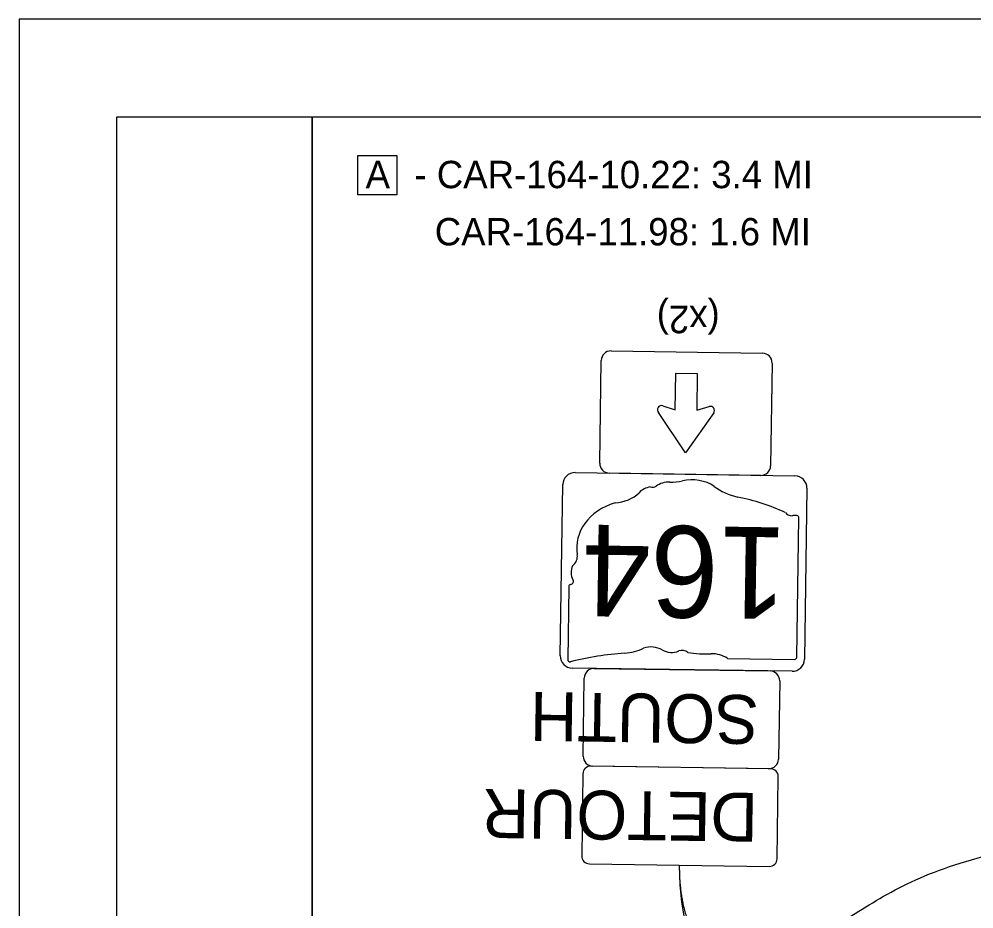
# Model space of a CAD drawing. Extents: x 0 to 1214, y 0 to 883.
# Drawn here: x 0 to 97.7, y 349 to 440 of the extents above; entities that cross this region are included whole.
import ezdxf

# ---------------------------------------------------------------- set-up
doc = ezdxf.new("R2010")
doc.units = 0
for name, color, linetype in [('GM_X_Minor_River', 7, 'Continuous'), ('GM_X_Section', 7, 'Continuous'), ('SH_Border', 7, 'Continuous'), ('SH_Cut_Line', 7, 'Continuous'), ('SH_Data', 7, 'Continuous')]:
    doc.layers.add(name, color=color, linetype=linetype)

msp = doc.modelspace()

# ---------------------------------------------------------------- linework, layer by layer
at = {"layer": 'GM_X_Minor_River'}
for p, q in [((60.603, 406.048), (76.102, 405.82)), ((59.434, 394.564), (59.589, 405.063)), ((77.087, 404.805), (76.932, 394.306)), ((67.172, 400.014), (67.227, 403.763)), ((67.227, 403.763), (69.415, 403.731)), ((69.415, 403.731), (69.36, 399.982)), ((65.894, 400.431), (67.172, 400.014)), ((69.36, 399.982), (70.647, 400.361)), ((68.2, 395.623), (65.466, 399.744)), ((71.104, 399.719), (68.2, 395.623)), ((75.917, 393.321), (60.419, 393.549)), ((79.613, 374.736), (79.823, 388.965)), ((56.28, 381.928), (56.17, 374.484)), ((56.282, 381.926), (56.28, 381.928)), ((72.516, 374.596), (79.379, 374.495)), ((58.874, 373.57), (76.873, 373.305)), ((57.742, 364.586), (57.86, 372.585)), ((77.858, 372.29), (77.74, 364.291)), ((76.725, 363.306), (58.727, 363.571))]:
    msp.add_line(p, q, dxfattribs=at)
for points in [[(56.919, 393.601), (79.417, 393.269)], [(55.393, 374.871), (55.651, 392.369)], [(80.648, 392.001), (80.391, 374.503)], [(79.122, 373.271), (56.625, 373.603)], [(57.715, 362.786), (57.592, 354.387)], [(76.925, 363.303), (58.527, 363.574)], [(77.589, 354.092), (77.713, 362.491)], [(58.38, 353.575), (76.778, 353.304)]]:
    msp.add_lwpolyline(points, dxfattribs=at)
for centre, radius, start, end in [((60.588, 405.048), 1, 89.1557, 179.1557), ((76.087, 404.819), 1, 359.1557, 89.1557), ((65.765, 400.034), 0.417, 71.95109, 224.16526), ((70.765, 399.96), 0.417, 324.56692, 106.36031), ((60.434, 394.549), 1, 179.1557, 269.1557), ((75.932, 394.32), 1, 269.1557, 359.1557), ((56.901, 392.351), 1.25, 89.1557, 179.1557), ((79.399, 392.019), 1.25, 359.1557, 89.1557), ((56.643, 374.853), 1.25, 179.1557, 269.1557), ((79.141, 374.521), 1.25, 269.1557, 359.1557), ((58.86, 372.57), 1, 89.1557, 179.1557), ((76.858, 372.305), 1, 359.1557, 89.1557), ((58.742, 364.571), 1, 179.1557, 269.1557), ((76.74, 364.306), 1, 269.1557, 359.1557), ((58.515, 362.774), 0.8, 89.1557, 179.1557), ((76.913, 362.503), 0.8, 359.1557, 89.1557), ((58.392, 354.375), 0.8, 179.1557, 269.1557), ((76.79, 354.104), 0.8, 269.1557, 359.1557)]:
    msp.add_arc(centre, radius, start, end, dxfattribs=at)
for centre, major_axis, start_param, end_param in [((68.858, 390.019), (-3.563, 0.053), 4.026481, 4.996735), ((65.057, 390.562), (-2.008, 0.03), 4.937069, 5.64225), ((64.858, 392.522), (-0.535, 0.008), 1.147584, 2.315152), ((66.555, 391.119), (-1.898, 0.028), 4.691044, 5.507374), ((66.872, 394.969), (-2.928, 0.043), 1.495662, 1.94098), ((75.012, 395.43), (-5.615, 0.083), 0.823519, 1.323587), ((60.782, 393.242), (-3.404, 0.05), 1.647645, 2.488434), ((69.391, 377.153), (-17.947, 0.264), 4.195997, 4.488961), ((63.295, 385.887), (-6.216, 0.092), 5.101752, 6.440018), ((79.095, 389.797), (-0.754, 0.011), 0.519207, 1.627899), ((79.49, 387.545), (-2.09, 0.031), 4.665946, 4.897461), ((79.553, 389.001), (-0.274, 0.004), 3.00124, 4.508301), ((55.391, 385.056), (-1.763, 0.026), 2.387724, 3.262537), ((58.93, 383.376), (-2.424, 0.036), 5.934695, 6.695948), ((56.558, 381.952), (-0.279, 0.004), 5.05454, 6.418171), ((56.348, 382.473), (-0.404, 0.006), 1.883978, 3.671073), ((61.417, 379.106), (-5, 0.074), 1.699011, 2.107814), ((64.702, 374.241), (-1.9, 0.028), 4.081561, 5.145723), ((66.774, 376.466), (-1.579, 0.023), 0.950623, 2.079405), ((67.865, 374.805), (-0.76, 0.011), 3.836095, 5.185415), ((56.429, 374.449), (-0.261, 0.004), 6.141152, 7.989035), ((64.237, 355.314), (-24.852, 0.366), 4.814394, 5.042369), ((70.126, 382.621), (-9.453, 0.139), 1.404758, 1.657858), ((70.857, 372.968), (-2.633, 0.039), 4.042523, 4.731795), ((79.344, 374.71), (-0.271, 0.004), 1.712693, 3.28349)]:
    msp.add_ellipse(centre, major_axis=major_axis, ratio=0.8, start_param=start_param, end_param=end_param, dxfattribs=at)
at = {"layer": 'GM_X_Section'}
msp.add_lwpolyline([(34.671, 426.037), (38.671, 426.037), (38.671, 422.037), (34.671, 422.037)], close=True, dxfattribs=at)
at = {"layer": 'SH_Border'}
for points in [[(10, 430), (30, 430), (30, 10), (10, 10)], [(30, 430), (670, 430), (670, 10), (30, 10)]]:
    msp.add_lwpolyline(points, close=True, dxfattribs=at)
at = {"layer": 'SH_Cut_Line'}
msp.add_lwpolyline([(0, 0), (680, 0), (680, 440), (0, 440)], close=True, dxfattribs=at)
at = {"layer": 'SH_Data'}
for points, degree in [([(67.579, 353.439), (67.579, 345.589), (76.872, 342.327), (95.836, 355.671), (148.431, 361.305), (164.284, 342.476), (185.838, 344.476), (186.923, 340.63)], 2), ([(67.579, 353.439), (67.579, 342.165), (77.813, 338.757), (77.813, 338.757), (94.678, 344.599), (112.516, 348.981), (137.165, 352.064), (154.678, 344.761), (174.381, 338.076), (180.945, 336.282), (186.915, 337.009), (186.923, 335.916)], 3)]:
    msp.add_open_spline(points, degree=degree, dxfattribs=at)

# ---------------------------------------------------------------- texts
at = {"layer": 'GM_X_Minor_River'}
for s, height, p in [('164', 9.375, (78.661, 387.979)), ('SOUTH', 5, (75.749, 370.821)), ('DETOUR', 5, (75.656, 360.821))]:
    msp.add_text(s, height=height, rotation=179.1557, dxfattribs=at).set_placement(p)
at = {"layer": 'GM_X_Section'}
for s, p in [('A', (35.47, 422.7)), ('- CAR-164-10.22: 3.4 MI', (40.47, 422.7)), ('  CAR-164-11.98: 1.6 MI', (40.47, 416.848))]:
    msp.add_text(s, height=2.8, dxfattribs=at).set_placement(p)
at = {"layer": 'SH_Data'}
msp.add_text('(x2)', height=2.8, rotation=180, dxfattribs=at).set_placement((71.718, 410.664))

doc.saveas('drawing.dxf')
